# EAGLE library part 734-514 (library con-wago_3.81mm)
Serie 734, Federleiste mit geraden Einlötstiften / Series 734, Female connector with straight solder pins Polzahl / Pole No.: 14 Bemessungsspannung / Rated Voltage: 160 V Nennstrom / Nominal Current: 10 A Lötstiftlänge: / Solder Pin Length: 3.8 mm Farbe / Color: orange / orange Stand: 01.01.2012. Die jeweils aktuellen Daten zu diesem Artikel finden Sie in unserem Produktkatalog, den Sie unter www.wago.com einsehen können. As of: 01/01/2012. Please find the newest data for this article in our product catalogue, which can be viewed under www.wago.com.
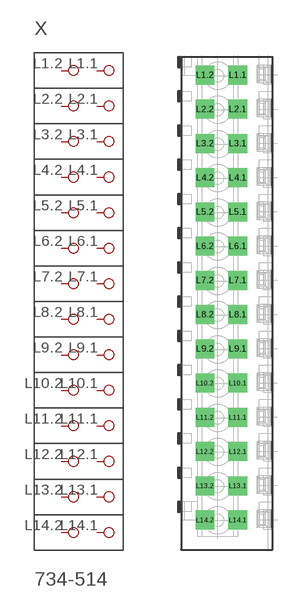
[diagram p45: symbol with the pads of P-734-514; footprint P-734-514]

Designator prefix X

## 734-514  [P-734-514]
L1.1  P1.1
L1.2  P1.2
L2.1  P2.1
L2.2  P2.2
L3.1  P3.1
L3.2  P3.2
L4.1  P4.1
L4.2  P4.2
L5.1  P5.1
L5.2  P5.2
L6.1  P6.1
L6.2  P6.2
L7.1  P7.1
L7.2  P7.2
L8.1  P8.1
L8.2  P8.2
L9.1  P9.1
L9.2  P9.2
L10.1  P10.1
L10.2  P10.2
L11.1  P11.1
L11.2  P11.2
L12.1  P12.1
L12.2  P12.2
L13.1  P13.1
L13.2  P13.2
L14.1  P14.1
L14.2  P14.2

## Footprint P-734-514 (pad centres in mm)
drill 1.4 square: L1.1 1.115,25.405; L1.2 -2.535,25.405; L2.1 1.115,21.595; L2.2 -2.535,21.595; L3.1 1.115,17.785; L3.2 -2.535,17.785; L4.1 1.115,13.975; L4.2 -2.535,13.975; L5.1 1.115,10.165; L5.2 -2.535,10.165; L6.1 1.115,6.355; L6.2 -2.535,6.355; L7.1 1.115,2.545; L7.2 -2.535,2.545; L8.1 1.115,-1.265; L8.2 -2.535,-1.265; L9.1 1.115,-5.075; L9.2 -2.535,-5.075; L10.1 1.115,-8.885; L10.2 -2.535,-8.885; L11.1 1.115,-12.695; L11.2 -2.535,-12.695; L12.1 1.115,-16.505; L12.2 -2.535,-16.505; L13.1 1.115,-20.315; L13.2 -2.535,-20.315; L14.1 1.115,-24.125; L14.2 -2.535,-24.125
